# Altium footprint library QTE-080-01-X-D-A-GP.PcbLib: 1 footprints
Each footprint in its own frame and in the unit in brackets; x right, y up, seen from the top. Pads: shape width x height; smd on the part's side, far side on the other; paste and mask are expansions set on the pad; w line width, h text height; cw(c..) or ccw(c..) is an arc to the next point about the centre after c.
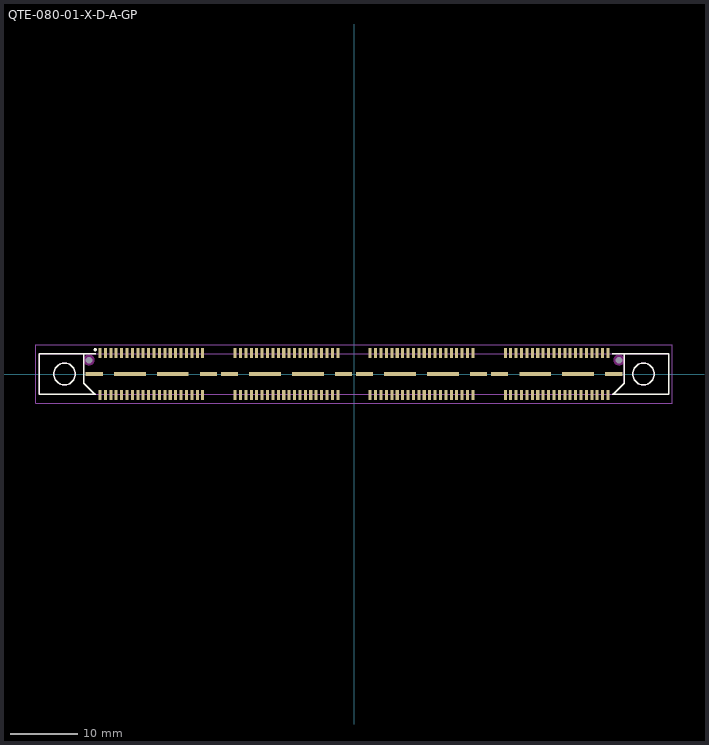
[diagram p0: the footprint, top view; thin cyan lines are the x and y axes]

## QTE-080-01-X-D-A-GP [mm] "0.80mm pitch, 160 pin, high speed terminal strip; w/guide posts"
height 4.27
pads (178):
  rect 0.45x1.45 smd mask+0: 1(-37.6,3.09) 2(-37.6,-3.09) 3(-36.8,3.09) 4(-36.8,-3.09) 5(-36,3.09) 6(-36,-3.09) 7(-35.2,3.09) 8(-35.2,-3.09) 9(-34.4,3.09) 10(-34.4,-3.09) 11(-33.6,3.09) 12(-33.6,-3.09) 13(-32.8,3.09) 14(-32.8,-3.09) 15(-32,3.09) 16(-32,-3.09) 17(-31.2,3.09) 18(-31.2,-3.09) 19(-30.4,3.09) 20(-30.4,-3.09) 21(-29.6,3.09) 22(-29.6,-3.09) 23(-28.8,3.09) 24(-28.8,-3.09) 25(-28,3.09) 26(-28,-3.09) 27(-27.2,3.09) 28(-27.2,-3.09) 29(-26.4,3.09) 30(-26.4,-3.09) 31(-25.6,3.09) 32(-25.6,-3.09) 33(-24.8,3.09) 34(-24.8,-3.09) 35(-24,3.09) 36(-24,-3.09) 37(-23.2,3.09) 38(-23.2,-3.09) 39(-22.4,3.09) 40(-22.4,-3.09) 41(-17.6,3.09) 42(-17.6,-3.09) 43(-16.8,3.09) 44(-16.8,-3.09) 45(-16,3.09) 46(-16,-3.09) 47(-15.2,3.09) 48(-15.2,-3.09) 49(-14.4,3.09) 50(-14.4,-3.09) 51(-13.6,3.09) 52(-13.6,-3.09) 53(-12.8,3.09) 54(-12.8,-3.09) 55(-12,3.09) 56(-12,-3.09) 57(-11.2,3.09) 58(-11.2,-3.09) 59(-10.4,3.09) 60(-10.4,-3.09) 61(-9.6,3.09) 62(-9.6,-3.09) 63(-8.8,3.09) 64(-8.8,-3.09) 65(-8,3.09) 66(-8,-3.09) 67(-7.2,3.09) 68(-7.2,-3.09) 69(-6.4,3.09) 70(-6.4,-3.09) 71(-5.6,3.09) 72(-5.6,-3.09) 73(-4.8,3.09) 74(-4.8,-3.09) 75(-4,3.09) 76(-4,-3.09) 77(-3.2,3.09) 78(-3.2,-3.09) 79(-2.4,3.09) 80(-2.4,-3.09) 81(2.4,3.09) 82(2.4,-3.09) 83(3.2,3.09) 84(3.2,-3.09) 85(4,3.09) 86(4,-3.09) 87(4.8,3.09) 88(4.8,-3.09) 89(5.6,3.09) 90(5.6,-3.09) 91(6.4,3.09) 92(6.4,-3.09) 93(7.2,3.09) 94(7.2,-3.09) 95(8,3.09) 96(8,-3.09) 97(8.8,3.09) 98(8.8,-3.09) 99(9.6,3.09) 100(9.6,-3.09) 101(10.4,3.09) 102(10.4,-3.09) 103(11.2,3.09) 104(11.2,-3.09) 105(12,3.09) 106(12,-3.09) 107(12.8,3.09) 108(12.8,-3.09) 109(13.6,3.09) 110(13.6,-3.09) 111(14.4,3.09) 112(14.4,-3.09) 113(15.2,3.09) 114(15.2,-3.09) 115(16,3.09) 116(16,-3.09) 117(16.8,3.09) 118(16.8,-3.09) 119(17.6,3.09) 120(17.6,-3.09) 121(22.4,3.09) 122(22.4,-3.09) 123(23.2,3.09) 124(23.2,-3.09) 125(24,3.09) 126(24,-3.09) 127(24.8,3.09) 128(24.8,-3.09) 129(25.6,3.09) 130(25.6,-3.09) 131(26.4,3.09) 132(26.4,-3.09) 133(27.2,3.09) 134(27.2,-3.09) 135(28,3.09) 136(28,-3.09) 137(28.8,3.09) 138(28.8,-3.09) 139(29.6,3.09) 140(29.6,-3.09) 141(30.4,3.09) 142(30.4,-3.09) 143(31.2,3.09) 144(31.2,-3.09) 145(32,3.09) 146(32,-3.09) 147(32.8,3.09) 148(32.8,-3.09) 149(33.6,3.09) 150(33.6,-3.09) 151(34.4,3.09) 152(34.4,-3.09) 153(35.2,3.09) 154(35.2,-3.09) 155(36,3.09) 156(36,-3.09) 157(36.8,3.09) 158(36.8,-3.09) 159(37.6,3.09) 160(37.6,-3.09)
  rect 2.55x0.65 smd mask+0: 161(-38.445,0) 164(-21.555,0) 165(-18.445,0) 168(-1.555,0) 169(1.555,0) 172(18.445,0) 173(21.555,0) 176(38.445,0)
  rect 4.7x0.65 smd mask+0: 162(-33.175,0) 163(-26.825,0) 166(-13.175,0) 167(-6.825,0) 170(6.825,0) 171(13.175,0) 174(26.825,0) 175(33.175,0)
  round 0.5 hole 1 unplated mask+0: 177(-39.24,2.04) 178(39.24,2.04)
Top Overlay:
  circle w0.25: c-38.3,3.6 r0.125
  circle w0.2: c42.85,0 r1.6
  circle w0.2: c-42.85,0 r1.6
  lines w0.2: -40,3 -40,-1.4 -38.4,-3 ; -38.2,-3 -46.6,-3 -46.6,3 -38.2,3 ; 38.2,-3 46.6,-3 46.6,3 38.2,3 ; 38.4,-3 40,-1.4 40,3
Keep-Out Layer:
  pour cut-out: 40.047,2.04 40.019,2.249 39.939,2.443 39.811,2.611 39.643,2.739 39.449,2.819 39.24,2.847 39.031,2.819 38.837,2.739 38.669,2.611 38.541,2.443 38.461,2.249 38.433,2.04 38.461,1.831 38.541,1.637 38.669,1.469 38.837,1.341 39.031,1.261 39.24,1.233 39.449,1.261 39.643,1.341 39.811,1.469 39.939,1.637 40.019,1.831
  pour cut-out: -38.433,2.04 -38.461,2.249 -38.541,2.443 -38.669,2.611 -38.837,2.739 -39.031,2.819 -39.24,2.847 -39.449,2.819 -39.643,2.739 -39.811,2.611 -39.939,2.443 -40.019,2.249 -40.047,2.04 -40.019,1.831 -39.939,1.637 -39.811,1.469 -39.643,1.341 -39.449,1.261 -39.24,1.233 -39.031,1.261 -38.837,1.341 -38.669,1.469 -38.541,1.637 -38.461,1.831
Mechanical 12:
  lines w0.001: -46.6,-3 -46.6,3 46.6,3 46.6,-3 -46.6,-3
Mechanical 13:
  circle w0.1: c42.85,0 r1.6
  circle w0.1: c-42.85,0 r1.6
  lines w0.1: -40,3 -46.6,3 -46.6,-3 -38.4,-3 ; -40,3 40,3 ; -40,3 -40,-1.4 -38.4,-3 ; -38.4,-3 38.4,-3 ; 38.4,-3 46.6,-3 46.6,3 40,3 ; 38.4,-3 40,-1.4 40,3
  text ".Designator" at 0,0 h1.52
Mechanical 15:
  lines w0.05: -47.1,-4.3 -47.1,4.3 47.1,4.3 47.1,-4.3 -47.1,-4.3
